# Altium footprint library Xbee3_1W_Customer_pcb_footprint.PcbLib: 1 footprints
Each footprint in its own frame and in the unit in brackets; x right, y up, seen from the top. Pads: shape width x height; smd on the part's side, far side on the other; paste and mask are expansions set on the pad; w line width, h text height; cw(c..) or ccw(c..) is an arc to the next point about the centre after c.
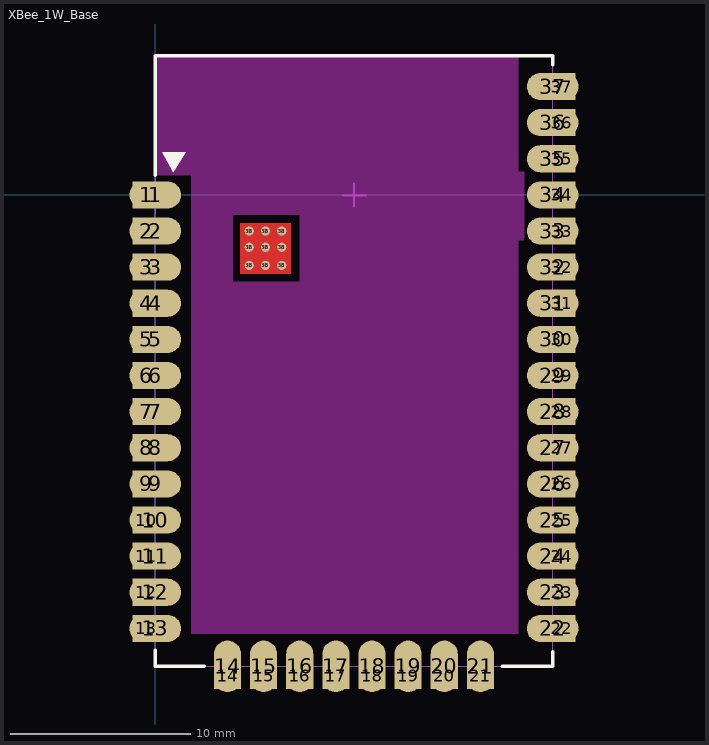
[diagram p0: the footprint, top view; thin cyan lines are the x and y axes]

## XBee_1W_Base [mm]
pads (84):
  rect 1.5x1.5 smd: 1(-0.508,0) 2(-0.508,-2) 3(-0.508,-4) 4(-0.508,-6) 5(-0.508,-8) 6(-0.508,-10) 7(-0.508,-12) 8(-0.508,-14) 9(-0.508,-16) 10(-0.508,-18) 11(-0.508,-20) 12(-0.508,-22) 13(-0.508,-24) 14(3.998,-26.608) 15(5.998,-26.608) 16(7.998,-26.608) 17(9.998,-26.608) 18(11.998,-26.608) 19(13.998,-26.608) 20(15.998,-26.608) 21(17.998,-26.608) 22(22.508,-24) 23(22.508,-22) 24(22.508,-20) 25(22.508,-18) 26(22.508,-16) 27(22.508,-14) 28(22.508,-12) 29(22.508,-10) 30(22.508,-8) 31(22.508,-6) 32(22.508,-4) 33(22.508,-2) 34(22.508,0) 35(22.508,2) 36(22.508,4) 37(22.5,6)
  oval 2.86x1.5 smd: 1(0,0) 2(0,-2) 3(0,-4) 4(0,-6) 5(0,-8) 6(0,-10) 7(0,-12) 8(0,-14) 9(0,-16) 10(0,-18) 11(0,-20) 12(0,-22) 13(0,-24) 22(22,-24) 23(22,-22) 24(22,-20) 25(22,-18) 26(22,-16) 27(22,-14) 28(22,-12) 29(22,-10) 30(22,-8) 31(22,-6) 32(22,-4) 33(22,-2) 34(22,0) 35(22,2) 36(22,4) 37(22,6)
  oval 1.5x2.86 smd: 14(3.998,-26.1) 15(5.998,-26.1) 16(7.998,-26.1) 17(9.998,-26.1) 18(11.998,-26.1) 19(13.998,-26.1) 20(15.998,-26.1) 21(17.998,-26.1)
  round 0.508 hole 0.254: 38(5.2,-3.9) 38(5.2,-2.9) 38(5.2,-2) 38(6.1,-3.9) 38(6.1,-2.9) 38(6.1,-2) 38(7,-3.9) 38(7,-2.9) 38(7,-2)
  round 0.2 smd: 38(6.2,-2.9)
Top Layer:
  region: 4.699,-4.369 7.493,-4.369 7.493,-1.575 4.699,-1.575
Top Layer keep-out:
  region: 2,0 2,-5.6 4.3,-5.6 4.3,0
  region: 0,7.7 20.1,7.7 20.1,-24.3 2,-24.3 2,-4.8 8,-4.8 8,-1.1 2,-1.1 2,1.1 0,1.1
Layer 1 keep-out:
  region: 20.422,1.295 20.422,-2.362 14.122,-2.362 14.097,-2.337 14.122,-2.311 14.122,1.295
Layer 2 keep-out:
  region: 20.422,1.295 20.422,-2.362 14.122,-2.362 14.097,-2.337 14.122,-2.311 14.122,1.295
Top Overlay:
  region: 1.696,2.362 0.396,2.362 0.996,1.262
  lines w0.2: 0,-25.2 0,-26.086 2.7,-26.086 ; 0,1.1 0,7.696 21.996,7.696 21.996,7.2 ; 19.2,-26.086 21.996,-26.086 21.996,-25.3
Top Paste:
  region: 6.351,-4.191 7.239,-4.191 7.239,-3.175 6.351,-3.175
  region: 4.953,-4.191 5.843,-4.191 5.843,-3.175 4.953,-3.175
  region: 6.351,-2.792 7.239,-2.792 7.239,-1.778 6.351,-1.778
  region: 4.953,-2.792 5.843,-2.792 5.843,-1.778 4.953,-1.778
  region: 4.699,-4.369 7.493,-4.369 7.493,-1.575 4.699,-1.575
Top Solder:
  region: 4.699,-4.369 7.493,-4.369 7.493,-1.575 4.699,-1.575
Bottom Solder:
  region: 7.548,-6.286 9.5,-6.286 9.5,-0.521 7.548,-0.521
  region: 2.6,-6.4 9.5,-6.4 9.5,-4.4 4.652,-4.4 4.652,-1.525 7.548,-1.525 7.548,-3.429 9.5,-3.429 9.5,0.4 2.6,0.4
Keep-Out Layer:
  region: 13.75,1.27 13.75,-2.515 20.396,-2.515 20.396,1.27
Mechanical 3:
  lines w0.051: 0,-26.086 21.996,-26.086 21.996,7.696 0,7.696 0,-26.086
  text ".Designator" at 0,1 h0.77
  text "14" at 3.288,-24.692 h1.27
  text "21" at 17.388,-24.692 h1.27
  text "37" at 19,5.3 h1.27
  text "1" at 1.5,-0.725 h1.27
Mechanical 20:
  lines w0.025: 0,-26.086 0,7.696 21.996,7.696 21.996,-26.086 0,-26.086
Mechanical 31:
  lines w0.1: -1,0 1,0 ; 0,-1 0,1 ; 10.389,-0.025 11.659,-0.025 ; 10.998,-0.635 10.998,0.635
